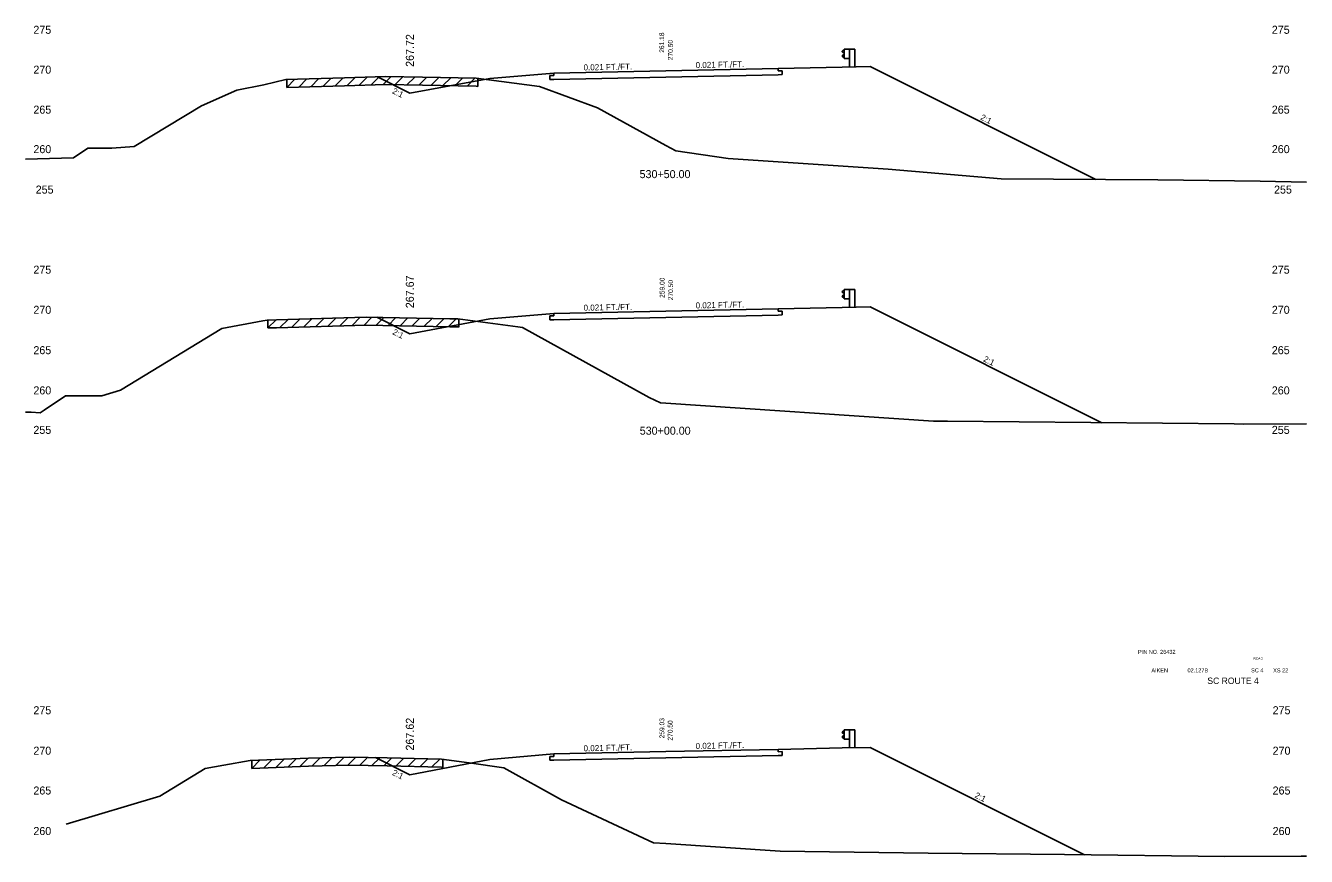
# Model space of a CAD drawing. Extents: x 883 to 1160, y 1002 to 4323.
# Drawn here: x 1000 to 1160, y 3492.4 to 3596.1 of the extents above; entities that cross this region are included whole.
import ezdxf

# ---------------------------------------------------------------- set-up
doc = ezdxf.new("R2010")
doc.units = 0
for name, color, linetype in [('Level 1', 7, 'Continuous'), ('Level 10', 7, 'Continuous'), ('Level 11', 7, 'Continuous'), ('Level 12', 7, 'Continuous'), ('Level 24', 7, 'Continuous'), ('Level 3', 7, 'Continuous'), ('Level 32', 7, 'Continuous'), ('Level 33', 7, 'Continuous'), ('Level 59', 7, 'Continuous'), ('Level 6', 7, 'Continuous'), ('Level 60', 7, 'Continuous'), ('Level 61', 7, 'Continuous'), ('Level 7', 7, 'Continuous')]:
    doc.layers.add(name, color=color, linetype=linetype)

msp = doc.modelspace()

# ---------------------------------------------------------------- linework, layer by layer
at = {"layer": 'Level 11'}
for p, q in [((1094, 3590.49), (1094, 3590.79)), ((1094.5, 3590.5), (1094, 3590.49)), ((1094.5, 3590.02), (1094.5, 3590.5)), ((1066, 3589.91), (1065.5, 3589.9)), ((1065.5, 3589.9), (1065.5, 3589.42)), ((1065.5, 3589.42), (1066, 3589.43)), ((1066, 3590.21), (1066, 3589.91)), ((1094, 3590.01), (1094.5, 3590.02)), ((1066, 3560.21), (1066, 3559.91)), ((1094, 3560.49), (1094, 3560.79)), ((1094.5, 3560.5), (1094, 3560.49)), ((1094, 3560.01), (1094.5, 3560.02)), ((1094.5, 3560.02), (1094.5, 3560.5)), ((1066, 3559.91), (1065.5, 3559.9)), ((1065.5, 3559.9), (1065.5, 3559.42)), ((1065.5, 3559.42), (1066, 3559.43)), ((1094, 3505.49), (1094, 3505.79)), ((1066, 3504.91), (1065.5, 3504.9)), ((1065.5, 3504.9), (1065.5, 3504.42)), ((1065.5, 3504.42), (1066, 3504.43)), ((1066, 3505.21), (1066, 3504.91)), ((1094.5, 3505.5), (1094, 3505.49)), ((1094, 3505.01), (1094.5, 3505.02)), ((1094.5, 3505.02), (1094.5, 3505.5))]:
    msp.add_line(p, q, dxfattribs=at)
at = {"layer": 'Level 12'}
for p, q in [((1080, 3589.72), (1066, 3589.43)), ((1094, 3590.01), (1080, 3589.72)), ((1094, 3560.01), (1080, 3559.72)), ((1080, 3559.72), (1066, 3559.43)), ((1080, 3504.72), (1066, 3504.43)), ((1094, 3505.01), (1080, 3504.72))]:
    msp.add_line(p, q, dxfattribs=at)
at = {"layer": 'Level 24'}
for p, q in [((1102.27, 3593.13), (1102, 3592.93)), ((1102, 3592.93), (1102, 3592.88)), ((1102, 3592.88), (1102.27, 3592.68)), ((1102, 3592.36), (1102.27, 3592.56)), ((1102, 3592.31), (1102, 3592.36)), ((1102.27, 3592.11), (1102, 3592.31)), ((1102.27, 3592.04), (1102.27, 3593.21)), ((1102.27, 3593.21), (1102.94, 3593.21)), ((1102.27, 3592.04), (1102.94, 3592.04)), ((1102.94, 3593.21), (1102.94, 3590.98)), ((1102.94, 3593.21), (1103.6, 3593.21)), ((1103.6, 3593.21), (1103.6, 3590.99)), ((1102.27, 3562.04), (1102.27, 3563.21)), ((1102.27, 3563.21), (1102.94, 3563.21)), ((1102.94, 3563.21), (1102.94, 3560.98)), ((1102.94, 3563.21), (1103.6, 3563.21)), ((1103.6, 3563.21), (1103.6, 3560.99)), ((1102.27, 3563.13), (1102, 3562.93)), ((1102, 3562.93), (1102, 3562.88)), ((1102, 3562.88), (1102.27, 3562.68)), ((1102, 3562.36), (1102.27, 3562.56)), ((1102, 3562.31), (1102, 3562.36)), ((1102.27, 3562.11), (1102, 3562.31)), ((1102.27, 3562.04), (1102.94, 3562.04)), ((1102.27, 3508.13), (1102, 3507.93)), ((1102, 3507.93), (1102, 3507.88)), ((1102, 3507.88), (1102.27, 3507.68)), ((1102, 3507.36), (1102.27, 3507.56)), ((1102, 3507.31), (1102, 3507.36)), ((1102.27, 3507.11), (1102, 3507.31)), ((1102.27, 3507.04), (1102.27, 3508.21)), ((1102.27, 3508.21), (1102.94, 3508.21)), ((1102.94, 3508.21), (1102.94, 3505.98)), ((1102.94, 3508.21), (1103.6, 3508.21)), ((1103.6, 3508.21), (1103.6, 3505.99)), ((1102.27, 3507.04), (1102.94, 3507.04))]:
    msp.add_line(p, q, dxfattribs=at)
at = {"layer": 'Level 59'}
for p, q in [((1066, 3590.21), (1080, 3590.5)), ((1080, 3590.5), (1094, 3590.79)), ((1066, 3560.21), (1080, 3560.5)), ((1080, 3560.5), (1094, 3560.79)), ((1080, 3505.5), (1094, 3505.79)), ((1066, 3505.21), (1080, 3505.5))]:
    msp.add_line(p, q, dxfattribs=at)
at = {"layer": 'Level 6'}
for p, q in [((1094, 3590.79), (1102, 3590.96)), ((1102, 3590.96), (1105.5, 3591.03)), ((1058, 3589.54), (1066, 3590.21)), ((1058, 3559.54), (1066, 3560.21)), ((1094, 3560.79), (1102, 3560.96)), ((1102, 3560.96), (1105.5, 3561.03)), ((1094, 3505.79), (1102, 3505.96)), ((1102, 3505.96), (1105.5, 3506.03)), ((1058, 3504.54), (1066, 3505.21))]:
    msp.add_line(p, q, dxfattribs=at)
at = {"layer": 'Level 60'}
for p, q in [((1029.78, 3588.74), (1032.49, 3589.4)), ((1032.49, 3589.4), (1039.84, 3589.62)), ((1039.84, 3589.62), (1044.97, 3589.77)), ((1044.97, 3589.77), (1049.56, 3589.7)), ((1049.56, 3589.7), (1056.28, 3589.56)), ((1056.28, 3589.56), (1059.45, 3589.15)), ((1059.45, 3589.15), (1064.2, 3588.53)), ((1021.96, 3586.13), (1026.38, 3588.1)), ((1026.38, 3588.1), (1029.78, 3588.74)), ((1064.2, 3588.53), (1071.46, 3585.88)), ((1013.58, 3581.05), (1021.96, 3586.13)), ((1071.46, 3585.88), (1080, 3581.18)), ((1005.98, 3579.65), (1007.78, 3580.84)), ((1007.78, 3580.84), (1010.77, 3580.84)), ((1010.77, 3580.84), (1013.58, 3581.05)), ((1080, 3581.18), (1081.21, 3580.51)), ((1000, 3579.48), (1005.98, 3579.65)), ((1081.21, 3580.51), (1087.78, 3579.53)), ((1087.78, 3579.53), (1107.77, 3578.22)), ((1107.77, 3578.22), (1121.85, 3577.01)), ((1121.85, 3577.01), (1141.44, 3576.87)), ((1141.44, 3576.87), (1154.24, 3576.73)), ((1154.24, 3576.73), (1160, 3576.59)), ((1024.5, 3558.32), (1029.63, 3559.29)), ((1029.63, 3559.29), (1030.16, 3559.38)), ((1030.16, 3559.38), (1031.34, 3559.43)), ((1031.34, 3559.43), (1042.55, 3559.76)), ((1042.55, 3559.76), (1053, 3559.54)), ((1053, 3559.54), (1053.98, 3559.52)), ((1053.98, 3559.52), (1061.49, 3558.52)), ((1061.49, 3558.52), (1062.08, 3558.44)), ((1062.08, 3558.44), (1077.9, 3549.7)), ((1011.84, 3550.64), (1024.5, 3558.32)), ((1009.51, 3549.94), (1011.84, 3550.64)), ((1002.3, 3548.14), (1005, 3549.94)), ((1005, 3549.94), (1009.51, 3549.94)), ((1077.9, 3549.7), (1079.32, 3549.04)), ((1079.32, 3549.04), (1080, 3549)), ((1080, 3549), (1113.42, 3546.77)), ((1000, 3547.87), (1000.7, 3547.88)), ((1000.7, 3547.88), (1001.8, 3547.78)), ((1001.8, 3547.78), (1002.3, 3548.14)), ((1113.42, 3546.77), (1115.15, 3546.74)), ((1115.15, 3546.74), (1150.98, 3546.41)), ((1150.98, 3546.41), (1152.2, 3546.4)), ((1152.2, 3546.4), (1160, 3546.43)), ((1024.76, 3503.83), (1028.05, 3504.4)), ((1028.05, 3504.4), (1035.36, 3504.68)), ((1035.36, 3504.68), (1040.44, 3504.83)), ((1040.44, 3504.83), (1045.17, 3504.73)), ((1045.17, 3504.73), (1051.97, 3504.56)), ((1051.97, 3504.56), (1055.39, 3504.1)), ((1055.39, 3504.1), (1059.73, 3503.48)), ((1016.77, 3499.94), (1022.45, 3503.4)), ((1022.45, 3503.4), (1024.76, 3503.83)), ((1059.73, 3503.48), (1066.96, 3499.48)), ((1005.07, 3496.43), (1016.77, 3499.94)), ((1066.96, 3499.48), (1078.44, 3494.13)), ((1078.44, 3494.13), (1080, 3494.03)), ((1080, 3494.03), (1094.26, 3493.08)), ((1094.26, 3493.08), (1112.77, 3492.83)), ((1112.77, 3492.83), (1129.77, 3492.67)), ((1129.77, 3492.67), (1149.8, 3492.43)), ((1149.8, 3492.43), (1159.33, 3492.47)), ((1159.33, 3492.47), (1160, 3492.47))]:
    msp.add_line(p, q, dxfattribs=at)
at = {"layer": 'Level 61'}
for p, q in [((1033.65, 3589.44), (1032.62, 3588.41)), ((1032.62, 3589.41), (1032.62, 3588.41)), ((1035.15, 3589.48), (1034.12, 3588.45)), ((1036.65, 3589.53), (1035.62, 3588.5)), ((1038.16, 3589.57), (1037.12, 3588.54)), ((1039.66, 3589.62), (1038.63, 3588.59)), ((1041.16, 3589.66), (1040.13, 3588.63)), ((1042.66, 3589.7), (1041.63, 3588.68)), ((1044.16, 3589.75), (1043.13, 3588.72)), ((1045.63, 3589.76), (1044.63, 3588.76)), ((1047.12, 3589.74), (1046.13, 3588.75)), ((1048.62, 3589.72), (1047.64, 3588.73)), ((1050.12, 3589.69), (1049.14, 3588.71)), ((1051.62, 3589.66), (1050.64, 3588.68)), ((1053.12, 3589.63), (1052.14, 3588.65)), ((1054.63, 3589.6), (1053.64, 3588.62)), ((1056.13, 3589.57), (1055.15, 3588.59)), ((1056.5, 3588.54), (1056.5, 3589.54)), ((1032.62, 3588.41), (1039.84, 3588.62)), ((1039.84, 3588.62), (1044.97, 3588.77)), ((1044.97, 3588.77), (1049.56, 3588.7)), ((1049.56, 3588.7), (1056.28, 3588.56)), ((1056.28, 3588.56), (1056.5, 3588.54)), ((1031.31, 3559.43), (1030.27, 3558.39)), ((1030.27, 3559.39), (1030.27, 3558.39)), ((1030.27, 3558.39), (1031.34, 3558.43)), ((1031.34, 3558.43), (1042.55, 3558.76)), ((1032.8, 3559.47), (1031.77, 3558.44)), ((1034.3, 3559.52), (1033.27, 3558.49)), ((1035.8, 3559.56), (1034.77, 3558.53)), ((1037.3, 3559.61), (1036.27, 3558.57)), ((1038.81, 3559.65), (1037.77, 3558.62)), ((1040.31, 3559.7), (1039.27, 3558.66)), ((1041.81, 3559.74), (1040.78, 3558.71)), ((1043.27, 3559.75), (1042.28, 3558.75)), ((1042.55, 3558.76), (1053, 3558.54)), ((1044.76, 3559.72), (1043.78, 3558.74)), ((1046.26, 3559.68), (1045.28, 3558.7)), ((1047.76, 3559.65), (1046.78, 3558.67)), ((1049.26, 3559.62), (1048.28, 3558.64)), ((1050.77, 3559.59), (1049.79, 3558.61)), ((1052.27, 3559.56), (1051.29, 3558.58)), ((1053.77, 3559.52), (1052.79, 3558.55)), ((1053, 3558.54), (1053.98, 3558.52)), ((1053.98, 3558.52), (1054.14, 3558.5)), ((1054.14, 3558.5), (1054.14, 3559.5)), ((1029.28, 3504.45), (1028.24, 3503.41)), ((1028.24, 3504.41), (1028.24, 3503.41)), ((1030.78, 3504.51), (1029.74, 3503.47)), ((1032.28, 3504.56), (1031.24, 3503.52)), ((1033.78, 3504.62), (1032.74, 3503.58)), ((1035.28, 3504.67), (1034.25, 3503.63)), ((1036.78, 3504.72), (1035.75, 3503.69)), ((1038.28, 3504.76), (1037.25, 3503.73)), ((1039.78, 3504.81), (1038.75, 3503.78)), ((1041.24, 3504.81), (1040.25, 3503.82)), ((1042.73, 3504.78), (1041.75, 3503.8)), ((1044.23, 3504.75), (1043.25, 3503.77)), ((1045.73, 3504.71), (1044.75, 3503.74)), ((1047.23, 3504.68), (1046.25, 3503.7)), ((1048.73, 3504.64), (1047.75, 3503.66)), ((1050.23, 3504.6), (1049.26, 3503.62)), ((1051.73, 3504.56), (1050.76, 3503.59)), ((1052.11, 3503.54), (1052.11, 3504.54)), ((1028.24, 3503.41), (1035.36, 3503.68)), ((1035.36, 3503.68), (1040.44, 3503.83)), ((1040.44, 3503.83), (1045.17, 3503.73)), ((1045.17, 3503.73), (1051.97, 3503.56)), ((1051.97, 3503.56), (1052.11, 3503.54))]:
    msp.add_line(p, q, dxfattribs=at)
at = {"layer": 'Level 7'}
for p, q in [((1105.5, 3591.03), (1133.71, 3576.92)), ((1043.95, 3589.74), (1048, 3587.72)), ((1048, 3587.72), (1058, 3589.54)), ((1105.5, 3561.03), (1134.43, 3546.56)), ((1043.86, 3559.73), (1048, 3557.67)), ((1048, 3557.67), (1058, 3559.54)), ((1105.5, 3506.03), (1132.28, 3492.64)), ((1043.72, 3504.76), (1048, 3502.62)), ((1048, 3502.62), (1058, 3504.54))]:
    msp.add_line(p, q, dxfattribs=at)

# ---------------------------------------------------------------- texts
at = {"layer": 'Level 1'}
for s, height, p in [('530+50.00', 1, (1076.7, 3577.1)), ('530+00.00', 1, (1076.72, 3545.07)), ('PIN NO. 26432', 0.5, (1138.97, 3517.71)), ('AIKEN', 0.5, (1140.64, 3515.4)), ('02.127B', 0.5, (1145.15, 3515.4)), ('SC 4', 0.5, (1153.09, 3515.4)), ('XS 22', 0.5, (1155.85, 3515.39)), ('SC ROUTE 4', 0.8, (1147.63, 3513.95))]:
    msp.add_text(s, height=height, dxfattribs=at).set_placement(p)
at = {"layer": 'Level 10'}
for s, p in [('261.18', (1079.77, 3592.75)), ('259.00', (1079.82, 3562.15)), ('259.03', (1079.79, 3507.16))]:
    msp.add_text(s, height=0.6, rotation=90, dxfattribs=at).set_placement(p)
at = {"layer": 'Level 3'}
for s, height, p in [(' 275', 1, (1000.6, 3595.12)), (' 275', 1, (1155.31, 3595.12)), (' 270', 1, (1000.6, 3590.14)), (' 270', 1, (1155.31, 3590.14)), (' 265', 1, (1000.6, 3585.15)), (' 265', 1, (1155.31, 3585.15)), (' 260', 1, (1000.6, 3580.22)), (' 260', 1, (1155.31, 3580.22)), (' 255', 1, (1000.89, 3575.17)), (' 255', 1, (1155.59, 3575.17)), (' 275', 1, (1000.6, 3565.17)), (' 275', 1, (1155.31, 3565.17)), (' 270', 1, (1000.6, 3560.16)), (' 270', 1, (1155.31, 3560.16)), (' 265', 1, (1000.6, 3555.12)), (' 265', 1, (1155.31, 3555.12)), (' 260', 1, (1000.6, 3550.1)), (' 260', 1, (1155.31, 3550.1)), (' 255', 1, (1000.6, 3545.17)), (' 255', 1, (1155.31, 3545.17)), ('ROAD', 0.3, (1153.38, 3516.98)), (' 275', 1, (1000.6, 3510.17)), (' 275', 1, (1155.41, 3510.17)), (' 270', 1, (1000.6, 3505.12)), (' 270', 1, (1155.41, 3505.12)), (' 265', 1, (1000.6, 3500.15)), (' 265', 1, (1155.41, 3500.15)), (' 260', 1, (1000.6, 3495.09)), (' 260', 1, (1155.41, 3495.09))]:
    msp.add_text(s, height=height, dxfattribs=at).set_placement(p)
at = {"layer": 'Level 32'}
for s, rotation, p in [('0.021 FT./FT.', 1.1916, (1069.71, 3590.54)), ('0.021 FT./FT.', 1.1916, (1083.71, 3590.83)), ('2:1', 333.435, (1045.73, 3587.73)), ('2:1', 333.435, (1119.21, 3584.45)), ('0.021 FT./FT.', 1.1916, (1083.71, 3560.83)), ('0.021 FT./FT.', 1.1916, (1069.71, 3560.54)), ('2:1', 333.435, (1045.76, 3557.65)), ('2:1', 333.435, (1119.57, 3554.27)), ('0.021 FT./FT.', 1.1916, (1069.71, 3505.54)), ('0.021 FT./FT.', 1.1916, (1083.71, 3505.83)), ('2:1', 333.435, (1045.73, 3502.63)), ('2:1', 333.435, (1118.49, 3499.81))]:
    msp.add_text(s, height=0.75, rotation=rotation, dxfattribs=at).set_placement(p)
at = {"layer": 'Level 33'}
for s, p in [('267.72', (1048.5, 3590.99)), ('267.67', (1048.5, 3560.86)), ('267.62', (1048.5, 3505.64))]:
    msp.add_text(s, height=1, rotation=90, dxfattribs=at).set_placement(p)
at = {"layer": 'Level 59'}
for p in [(1080.85, 3591.59), (1080.88, 3561.62), (1080.82, 3506.65)]:
    msp.add_text(' 270.50', height=0.6, rotation=90, dxfattribs=at).set_placement(p)

doc.saveas('drawing.dxf')
